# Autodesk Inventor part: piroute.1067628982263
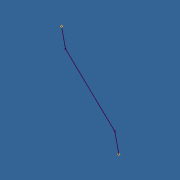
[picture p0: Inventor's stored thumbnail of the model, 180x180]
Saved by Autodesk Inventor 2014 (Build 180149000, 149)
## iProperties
StyleName: _Piping Style 19
Company: Autodesk, Inc.
Shininess: 64.0
Length Units: 11272
Angle Units: 11279
Time Units: 11290
Mass Units: 11286
Length Display Precision: 3
Angle Display Precision: 2
Compacted: True
TPVersion: 11.0.2
Part Number: piroute.1067628982263
Document SubType Name: Tube & Pipe
Created: 2003-10
Designer: Autodesk, Inc.
Manufacturer: Standard
Standards Organization: Custom
Density: 1 g/cm^3
Material: Generic
Appearance: Default
Density: 0.0
Volumn: 0.0
Area: 0.0
PropertySet Name: Model Information
Control State: 0
Master: False
Checked Out: False
ActiveState: True
BendRadius: UnInitValue
CouplingKey: V3#0DC1AE02-7BBF-4CCF-8498-581434B0A765#8
DefaultBendRadius: 2.000 in
Diameter: 2
DiameterType: Nominal
Elbow45Key: UnInitValue
Elbow90Key: UnInitValue
EndFittingKey: UnInitValue
Ending: UnInitValue
FittingMaterial: UnInitValue
FittingStandard: UnInitValue
FlangeKey: UnInitValue
Gap: UnInitValue
GasketKey: UnInitValue
ID: UnInitValue
IntermediateSegmentsInc: 0.100 in
IntermediateSegmentsMax: 100.000 in
IntermediateSegmentsMin: 0.000 in
IsButtWelded: UnInitValue
IsFlanged: UnInitValue
Material: UnInitValue
MixedUnits: UnInitValue
Name: Large Copper Tubing
OD: UnInitValue
PipeKey: V3#44B182C9-4BCE-4825-BB4D-596143122252#24
PipeType: Tubing
PipingComponentColor: As Material
RoundUpValue: UnInitValue
RouteDirection45: False
RouteDirection90: True
Schedule: L
ShowGap: UnInitValue
Standard: UnInitValue
StartFittingKey: UnInitValue
SuppressEndFitting: UnInitValue
SuppressStartFitting: UnInitValue
TerminationSegmentsInc: 0.100 in
TerminationSegmentsMax: 100.000 in
TerminationSegmentsMin: 0.000 in
UseFlangsForCouplings: UnInitValue
UseSubASM: UnInitValue
_ComponentInfo: <CS><C N="Pipe" R="2.698750" OR="2.698750" IR="2.520950" PL="PL" PartType="pipe" SymKey="" PN="ASTM B 88 Tube 2 - Type L"><CO N="1"><FE V="0"/><FD V="0"/><ET V=
Author: Autodesk, Inc.
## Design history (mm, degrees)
workpoint "Work Point1"
workpoint "Work Point4"
workplane "Work Plane1"
workplane "Work Plane2"
sketch "3D Sketch1" dims "d0" = 50.8 (= B), "d1" = 50.8 (= B)
other parameters: "B" = 50.8 [user parameter; used in 2 equation terms]
